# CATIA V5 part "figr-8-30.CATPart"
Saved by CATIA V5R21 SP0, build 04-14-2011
Part number: Part1
Bounding box of the stored display mesh (mm): x -50 to 50, y -75 to 125, z 0 to 40
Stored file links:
  D:\CATIA V5R21 E-RESOURCES\CATIA-V5R21\catia-v5r21-prt\c08-catia-v5r20-prt\c08-catia-v5r21-figr-8-30.CATPart
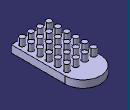
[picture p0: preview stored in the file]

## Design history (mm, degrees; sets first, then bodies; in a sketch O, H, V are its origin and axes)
Body1 (main body)
  Sketch1 on xy-plane, origin (0, 0, 0), H (1, 0, 0), V (0, 1, 0)
    line L1 (50, 75) -> (50, -75)
    line L2 (50, -75) -> (-50, -75)
    line L3 (-50, -75) -> (-50, 75)
    arc A1 centre (0, 75) radius 50 from (-50, 75) to (50, 75) cw
    point P5 (0, 75)
    axis line L4 (50, -75) -> (-50, 75)
    length L2 = 100
    distance P5 L2 = 150
    horizontal: L2 H
    vertical: L1 V, L3 V
    tangency: A1 L3, A1 L1
    midpoint: O L4
  Pad1: profile Sketch1, direction (0, 0, 1), length 20
  Sketch2 on face of Pad1, origin (0, 0, 20), H (1, 0, 0), V (0, 1, 0)
    circle A1 centre (35, -60) radius 7.5
    point P1 (35, -60)
    reference projected line E1 (-50, -75) -> (50, -75) from edge [face of Pad1 | face of Pad1]
    reference projected line E2 (50, -75) -> (50, 75) from edge [face of Pad1 | face of Pad1]
    distance P1 E1 = 15
    distance P1 E2 = 15
    radius A1 = 7.5
  Pad2: profile Sketch2, direction (0, 0, 1), length 20
  RectPattern1: of Pad2, direction 1 instances 4, spacing 25, along edge [face of Pad1 | face of Pad1] reversed, direction 2 instances 6, spacing 25, along edge [face of Pad1 | face of Pad1]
